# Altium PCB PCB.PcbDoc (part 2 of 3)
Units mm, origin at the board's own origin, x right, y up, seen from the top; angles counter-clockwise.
Board outline 43.18 x 22.86 mm, 6 copper layers (TOP, L2_GND, L3_SIG, L4_PWR, L5_GND, BOTTOM), stack 1.573 mm thick; 127 components, 116 nets, 532 pads, 386 vias.
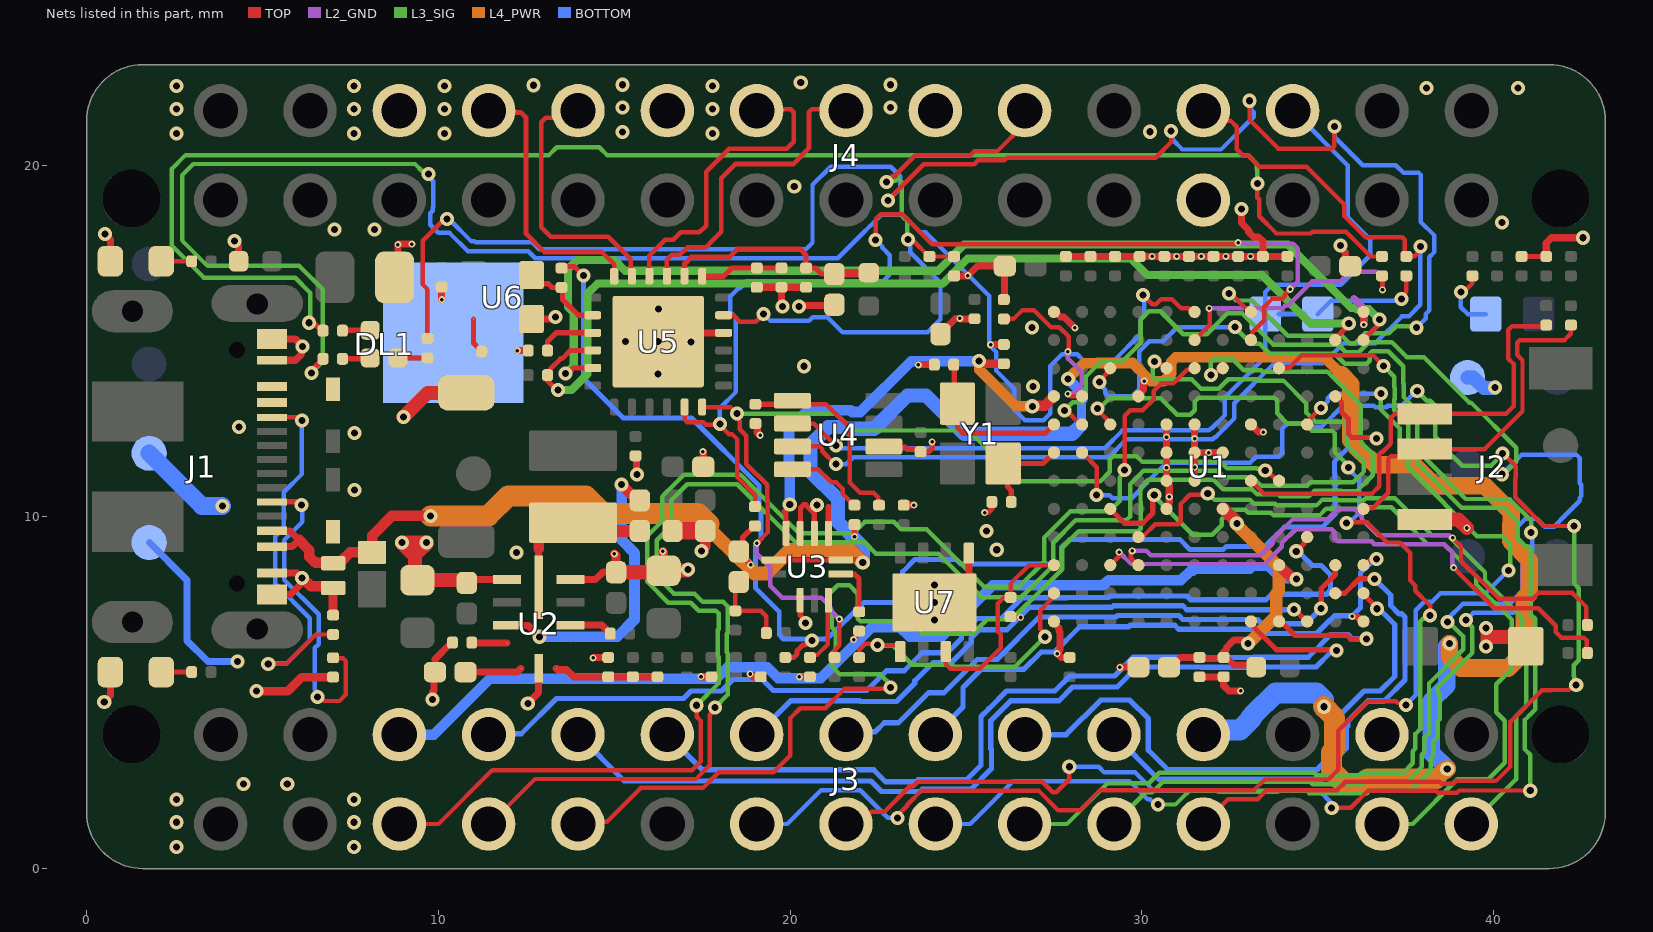
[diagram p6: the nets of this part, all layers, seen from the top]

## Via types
v1: diameter 0.4, hole 0.2, TOP to BOTTOM, tented both sides, 318 vias
v2: diameter 0.2, hole 0.1, TOP to L2_GND, tented both sides, 68 vias

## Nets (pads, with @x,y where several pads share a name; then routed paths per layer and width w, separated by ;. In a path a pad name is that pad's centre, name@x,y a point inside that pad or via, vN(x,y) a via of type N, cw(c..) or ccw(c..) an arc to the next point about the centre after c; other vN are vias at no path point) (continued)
+VBUS: D3.1 D8.A J1.A4 J1.A9 J1.B4 J1.B9 J3.23 TP_VUSB1.X U3.6 U3.11 | length 77.3
  TOP w0.15: U3.11@19.541,8.778 U3.6@21.436,8.778 ; U3.6@21.439,8.78 21.925,8.78 21.999,8.706 v1(22.066,8.706)
  TOP w0.2: J1.A9@5.276,9.155 5.844,9.155 6.039,9.35 5.784,9.605 J1.B4@5.276,9.605
  TOP w0.3: 6.039,9.35 6.333,9.056 6.333,8.87 6.508,8.695 6.966,8.695 7.005,8.733 7.233,8.733 7.494,8.994 D8.A@8.115,8.994 8.115,9.469 8.675,10.029 v1(9.772,10.029)
  L4_PWR w0.3: v1(27.902,13.927) 28.346,14.37 28.721,14.37 28.727,14.377 29.741,14.377 30.258,13.859 30.617,13.859 30.844,14.086 30.844,14.41 30.969,14.536 35.183,14.536 35.682,14.037
  L4_PWR w0.4: 17.7,9.8 17.7,9.677 18.649,8.728 18.657,8.728 18.994,8.391 19.325,8.391 19.99,9.055 21.718,9.055 v1(22.066,8.706)
  L4_PWR w0.5: 35.682,14.037 35.941,13.778 35.941,12.182 36.1,12.023 36.1,11.988 36.438,11.65 36.474,11.65 36.635,11.489 37.734,11.489 38.331,10.892 39.746,10.892 40.502,10.136 40.502,9.806 40.492,9.796 40.492,9.318 40.502,9.308 40.502,9.292 41.02,8.774 41.02,7.824 40.879,7.683 40.879,6.163 40.422,5.706 39.07,5.706 38.744,6.033 v1(38.744,6.396) ; 38.344,2.551 38.593,2.8 38.645,2.8 v1(38.684,2.84)
  L4_PWR w0.6: v1@9.773,10.029 11.417,10.029 11.987,10.599 14.201,10.599 14.7,10.1 17.4,10.1 17.7,9.8 ; v1(35.175,4.604) 35.477,4.302 35.477,3.395 35.39,3.308 35.39,2.789 35.757,2.422 36.3,2.422 36.429,2.551 38.344,2.551
  BOTTOM w0.25: 28.258,12.6 28.283,12.625 28.283,13.303 28.308,13.328
  BOTTOM w0.3: v1(27.902,13.927) 28.308,13.522 28.308,13.328
  BOTTOM w0.4: v1(22.066,8.706) 22.066,9.145 21.358,9.853 21.358,10.509 20.584,11.284 20.584,12.058 21.033,12.508 21.083,12.558 21.52,12.558 21.57,12.508 22.392,12.508 23.335,13.45 23.867,13.45 24.951,12.366 28.023,12.366 28.258,12.6
  BOTTOM w0.5: TP_VUSB1.X@1.778,11.811 3.276,10.313 v1(3.858,10.313) ; v1(38.684,2.84) 38.668,2.856 38.668,2.866 38.233,3.301 38.233,4.773 38.667,5.207 38.667,6.319 v1(38.744,6.396)
  BOTTOM w0.6: J3.23@31.75,3.81 31.88,3.94 32.792,3.94 33.103,4.251 33.103,4.302 33.179,4.377 33.179,4.38 33.798,5 34.963,5 35.168,4.795 35.168,4.613 35.176,4.605 v1(35.175,4.604)
A0_1: J3.7 U1.J10 | length 28.3
  TOP w0.15: v1(34.391,9.024) 34.398,9.024 34.611,9.237 34.611,9.285 34.702,9.376 U1.J10@34.702,9.43
  BOTTOM w0.15: J3.7@11.43,3.81 11.457,3.837 12.355,3.837 13.356,4.838 16.968,4.838 17.18,5.05 18.05,5.05 18.378,5.378 19.209,5.378 19.523,5.064 22.181,5.064 22.745,5.628 23.245,5.628 23.757,6.14 24.471,6.14 24.874,6.542 24.874,6.673 25.312,7.111 26.008,7.111 26.603,7.707 27.886,7.707 27.89,7.71 29.037,7.71 29.079,7.752 31.283,7.752 31.388,7.646 33.533,7.646 33.687,7.8 35.247,7.8 35.365,7.918 35.365,8.357 35.101,8.621 34.848,8.621 34.445,9.024 v1(34.391,9.024)
A1_1: J3.9 U1.M8 | length 27.6
  TOP w0.15: U1.M8@33.102,7.03 33.102,6.976 33.198,6.88 33.198,6.86 33.835,6.223 35.517,6.223 v1(35.54,6.199)
  BOTTOM w0.15: J3.9@13.97,3.81 15.285,2.495 22.303,2.495 22.602,2.195 23.695,2.195 23.758,2.258 25.139,2.258 25.726,2.844 25.726,3.394 25.708,3.412 25.708,4.208 25.925,4.426 25.925,4.429 26.269,4.772 27.639,4.772 28.035,5.168 29.301,5.168 29.869,5.736 31.687,5.736 31.699,5.724 33.298,5.724 33.309,5.736 34.957,5.736 35.373,6.151 35.492,6.151 v1(35.54,6.199)
A2_1: J3.11 U1.M9 | length 25.7
  TOP w0.15: U1.M9@33.902,7.03 33.957,7.03 34.356,6.63 35.313,6.63 35.318,6.635 35.833,6.635 35.943,6.525 36.382,6.525 v1(36.393,6.536)
  BOTTOM w0.15: J3.11@16.51,3.81 17.511,2.809 22.381,2.809 22.717,2.472 23.58,2.472 23.643,2.535 25.025,2.535 25.431,2.941 25.431,4.323 25.648,4.541 25.648,4.543 26.154,5.049 27.524,5.049 27.954,5.479 29.22,5.479 29.754,6.013 31.802,6.013 31.813,6.001 33.183,6.001 33.194,6.013 34.733,6.013 35.374,6.653 35.859,6.653 35.976,6.536 v1(36.393,6.536)
A3_1: J3.13 U1.M10 | length 17.5
  TOP w0.15: v1(34.333,7.363) 34.353,7.363 34.687,7.03 U1.M10@34.702,7.03
  BOTTOM w0.15: J3.13@19.05,3.81 20.012,4.772 21.988,4.772 22.008,4.753 23.027,4.753 23.548,5.274 23.548,5.342 24.069,5.863 24.586,5.863 25.151,6.427 25.151,6.558 25.386,6.793 26.164,6.793 26.8,7.43 28.001,7.43 28.005,7.433 29.152,7.433 29.193,7.475 31.168,7.475 31.279,7.363 v1(34.333,7.363)
A4_1: J3.15 U1.K11 | length 16.6
  TOP w0.15: v1(35.091,7.398) 35.103,7.41 35.103,7.964 35.502,8.363 U1.K11@35.502,8.63
  BOTTOM w0.15: J3.15@21.59,3.81 21.676,3.896 22.425,3.896 22.678,4.148 23.081,4.148 23.935,5.003 24.377,5.003 25.323,5.949 25.879,5.949 27.083,7.153 28.116,7.153 28.12,7.156 29.267,7.156 29.308,7.198 31.053,7.198 31.165,7.086 33.293,7.086 33.418,6.961 34.654,6.961 v1(35.091,7.398)
A5_1: J3.17 U1.K12 | length 16.2
  TOP w0.15: U1.K12@36.302,8.63 36.357,8.63 36.478,8.751 36.631,8.751 v1(36.679,8.799)
  BOTTOM w0.15: J3.17@24.13,3.81 24.915,4.595 24.915,5.149 25.437,5.672 26.65,5.672 27.142,6.163 27.518,6.163 28.234,6.879 29.629,6.879 29.67,6.921 30.938,6.921 31.054,6.805 33.183,6.805 33.304,6.684 34.97,6.684 35.268,6.983 ; 35.27,6.983 35.477,7.191 35.991,7.191 36.218,7.418 36.218,8.414 36.446,8.643 36.455,8.643 36.611,8.799 v1(36.679,8.799)
A6_1: J3.19 U1.L12 | length 16.7
  TOP w0.15: U1.L12@36.302,7.83 36.302,7.802 36.686,7.418 v1(36.686,7.39)
  BOTTOM w0.15: J3.19@26.67,3.81 27.85,3.81 28.835,4.796 29.656,4.796 30.186,4.265 30.186,3.368 30.738,2.816 34.987,2.816 35.338,3.167 35.338,3.337 35.496,3.495 35.496,4.072 35.589,4.165 35.589,4.308 35.678,4.397 35.678,4.413 35.878,4.613 36.316,5.051 36.778,5.051 37.193,5.466 37.193,6.939 36.743,7.39 v1(36.686,7.39)
A7_1: J3.21 U1.L11 | length 15.1
  TOP w0.15: U1.L11@35.502,7.83 35.769,7.83 36.18,8.241 v1(36.62,8.241)
  BOTTOM w0.15: J3.21@29.21,3.81 30.481,2.539 35.101,2.539 35.615,3.052 35.615,3.222 35.814,3.421 35.814,3.998 35.866,4.05 35.866,4.193 35.955,4.283 35.955,4.299 36.431,4.774 36.893,4.774 37.482,5.364 37.482,7.157 37.394,7.245 37.313,7.245 37.078,7.481 37.078,7.783 v1(36.62,8.241)
ANEN_SPEED: J4.19 R26.1 R30.1 U5.23 | length 18.2
  TOP w0.127: U5.23@18.11,15.735 18.393,15.735 18.574,15.554 19.025,15.554 v1(19.243,15.772) ; v1(22.747,19.526) 22.921,19.7 22.973,19.7 23.556,20.284 25.132,20.284 25.241,20.392 25.885,20.392 26.67,21.177 J4.19@26.67,21.59 ; v1(23.356,17.888) 23.408,17.835 23.52,17.835 23.95,17.406 R30.1@24.665,17.406
  L3_SIG w0.127: v1(22.747,19.526) 22.786,19.566 23.01,19.566 23.07,19.625 23.179,19.515 23.179,18.559 23.23,18.508 ; 23.23,18.508 23.336,18.402 23.336,17.907 v1(23.356,17.888)
  BOTTOM w0.127: v1(19.243,15.772) 19.443,15.572 20.533,15.572 20.641,15.68 21.062,15.68 21.492,15.25 23.907,15.25 24.277,15.62 24.277,16.668 23.419,17.526 23.419,17.751 23.356,17.814 v1(23.356,17.888)
AREF_1: J3.5 U1.K9 | length 28.8
  TOP w0.3: U1.K9@33.902,8.63 34.284,8.249 34.38,8.249 v1(34.399,8.23)
  BOTTOM w0.25: 31.446,8.475 31.471,8.5 33.076,8.5 33.162,8.586 33.591,8.586 33.947,8.23 v1(34.399,8.23)
  BOTTOM w0.3: J3.5@8.89,3.81 9.871,3.81 11.463,5.402 17.904,5.402 18.232,5.73 19.355,5.73 19.668,5.416 20.868,5.416 22.32,6.867 23.127,6.867 23.4,6.594 24.305,6.594 24.584,6.873 24.584,6.881 25.762,8.059 27.741,8.059 27.744,8.062 28.891,8.062 28.949,8.121 28.978,8.121 29.054,8.196 31.113,8.196 31.391,8.475 31.446,8.475
CANH_1: J4.23 R8.2 U4.7 | length 30.7
  TOP w0.127: U4.7@20.165,12.006 20.84,12.006 20.914,11.931 20.914,11.866 21.276,11.504 v1(21.305,11.504) ; J4.23@31.75,21.59 32.128,21.59 32.448,21.269 32.522,21.269 32.7,21.092 32.7,20.453 32.886,20.266 33.038,20.266 33.344,19.961 34.684,19.961 35.759,18.885 35.759,18.555 36,18.314 36.361,17.953 37.406,17.953 37.481,17.878 37.481,17.406 37.491,17.416 37.754,17.416 37.877,17.539 37.877,17.643 v1(37.929,17.695)
  BOTTOM w0.127: v1(21.305,11.504) 21.6,11.504 21.793,11.697 29.058,11.697 29.566,12.206 32.014,12.206 32.076,12.267 32.097,12.267 32.631,12.801 32.631,13.236 33.759,14.365 35.164,14.365 35.736,14.937 36.632,14.937 37.396,15.7 37.587,15.7 37.92,16.033 37.92,17.686 v1(37.929,17.695)
CANL_1: J4.25 SJ1.1 U4.6 | length 25.3
  TOP w0.127: U4.6@20.165,12.656 20.677,12.656 v1(21.302,12.031)
  BOTTOM w0.127: v1(21.302,12.031) 21.376,12.031 21.449,11.957 21.476,11.957 28.948,11.957 29.45,12.46 31.909,12.46 31.97,12.521 31.989,12.521 32.365,12.897 32.365,13.406 33.506,14.547 SJ1.1@33.506,15.769 33.506,16.396 33.707,16.596 35.653,16.596 36.5,17.443 36.5,17.879 35.859,18.52 35.859,19.994 J4.25@34.29,21.563
CC1_1: J1.A5 R10.2 | length 11.5
  TOP w0.127: v1(5.164,5.821) 5.674,5.821 6.511,6.658 R10.2@7.008,6.658 ; J1.A5@5.276,12.83 6.038,12.83 v1(6.121,12.747)
  BOTTOM w0.127: v1(5.164,5.821) 5.674,5.821 6.341,6.489 6.341,7.124 5.359,8.106 5.359,9.442 5.6,9.683 5.6,10.7 6.121,11.221 v1(6.121,12.747)
CC2_1: J1.B5 R9.2 | length 9.2
  TOP w0.127: v1(6.57,4.877) 6.644,4.877 6.753,4.767 7.186,4.767 7.37,4.95 7.37,5.902 7.295,5.976 7.113,5.976 R9.2@7.1,5.99
  TOP w0.15: J1.B5@5.276,10.43 5.951,10.43 6.043,10.338 v1(6.109,10.338)
  BOTTOM w0.127: v1(6.109,10.338) 6.133,10.314 6.133,9.857 5.613,9.337 5.613,8.212 6.595,7.229 6.595,6.383 6.489,6.277 6.489,5.088 6.517,5.059 6.517,4.929 v1(6.57,4.877)
ETH_RX_1_N: J4.15 U5.3 | length 8.8
  TOP w0.133: U5.3@16.495,16.851 16.495,17.313 16.519,17.338 16.632,17.451 16.864,17.451 17.072,17.659 17.6,17.659 17.793,17.852 18.047,18.106 18.047,19.636 18.444,20.034 20.086,20.034 20.537,20.484 20.537,21.512 20.615,21.59 J4.15@21.59,21.59
ETH_RX_1_P: J4.13 U5.4 | length 8.9
  TOP w0.133: U5.4@16,16.845 16,17.431 16.453,17.884 16.685,17.884 16.893,18.092 17.421,18.092 17.614,18.285 17.614,19.816 18.265,20.467 19.907,20.467 20.103,20.664 20.103,21.512 20.025,21.59 J4.13@19.05,21.59
ETH_TX_1_N: J4.9 U5.5 | length 7.6
  TOP w0.133: J4.9@13.97,21.59 13.726,21.346 13.053,21.346 12.926,21.219 12.926,18.234 13.194,17.966 14.83,17.966 15.105,17.692 15.231,17.565 15.467,17.329 15.467,16.879 U5.5@15.5,16.845
ETH_TX_1_P: J4.7 U5.6 | length 7.8
  TOP w0.133: J4.7@11.43,21.59 11.619,21.401 11.72,21.502 12.347,21.502 12.493,21.355 12.493,18.054 13.014,17.533 14.65,17.533 14.925,17.258 15.003,17.18 15.003,16.848 U5.6@15,16.845
GND: C1.1 C2.1 C3.1 C4.1 C5.1 C6.1 C7.1 C8.1 C9.2 C10.1 C11.1 C12.1 C13.1 C14.1 C17.1 C18.1 C20.2 C21.1 C23.1 C24.1 C25.2 C26.1 C27.1 C29.1 C30.1 C32.1 C33.1 C34.1 C35.1 C36.1 C37.1 C40.1 C42.1 C43.1 C44.1 C45.1 C46.1 C47.1 C48.1 C49.1 C51.1 D1.1 D2.1 D3.2 D6.1 DL2.C DL3.C GND1.X GND2.X J1.A1 J1.A12 J1.B1 J1.B12 J2.1 J3.27 J4.5 J4.11 J4.17 J4.24 PB1.1 QR1.PAD R4.1 R9.1 R10.1 R13.2 R15.2 R17.1 R21.2 R22.2 R29.1 R30.2 R31.2 R32.2 R33.1 R37.1 R42.2 R46.2 U1.A1 U1.A12 U1.D4 U1.E5 U1.E6 U1.E8 U1.F5 U1.F6 U1.F7 U1.G5 U1.G6 U1.H5 U1.M1 U1.M12 U2.1 U2.6 U2.11 U3.2 U4.2 U5.22 U5.25 U6.2 U7.5 U7.9 | length 80.6
  TOP w0.15: v2(18.879,8.638) 18.879,8.649 18.562,8.967 18.544,8.967 18.544,9.077 18.653,9.185 18.653,9.414 18.985,9.746 R29.1@19,9.746 ; v2(20.262,5.456) R42.2@20.565,5.456 ; U3.2@20.289,7.63 20.289,7.205 20.442,7.052 v1(20.442,6.986) ; v2(21.807,6.514) 21.807,6.527 21.873,6.594 21.873,6.676 21.953,6.756 C9.2@21.965,6.756 ; v2(21.832,9.439) R22.2@21.832,9.746 ; U4.2@22.665,12.006 22.69,11.98 23.274,11.98 23.327,11.926 23.644,11.926 C40.1@23.715,11.856 23.951,11.856 24.039,11.943 v2(24.039,12.133) ; v2(25.53,10.124) 25.54,10.134 25.636,10.134 25.738,10.235 C25.2@25.738,10.426 ; R37.1@26.269,7.165 26.292,7.141 v2(26.552,7.141) ; R46.2@40.8,17.406 C1.1@41.5,17.406
  TOP w0.2: v1@0.432,4.737 v1(0.5,4.737) 0.5,4.754 0.675,4.929 DL2.C@0.675,5.59 ; v1(0.52,18.051) 0.52,18.047 0.675,17.892 DL3.C@0.675,17.27 ; v1(4.202,17.841) 4.321,17.723 R4.1@4.321,17.27 ; J1.A12@5.276,7.795 5.801,7.795 6.083,8.078 6.083,8.168 6.122,8.206 v1(6.122,8.26) 6.122,8.267 6.001,8.388 5.995,8.388 5.979,8.405 J1.B1@5.276,8.405 ; J1.B12@5.276,14.455 5.933,14.455 6.105,14.627 6.105,14.814 v1(6.143,14.852) 5.93,15.065 J1.A1@5.276,15.065 ; C2.1@8.758,16.813 8.851,16.907 v2(8.851,17.741) 8.87,17.759 v2@9.198,17.759 ; v1(9.838,4.811) 9.838,5.024 9.87,5.056 9.87,5.557 C51.1@9.901,5.589 9.901,5.955 10.304,6.358 10.345,6.358 10.4,6.413 R15.2@10.4,6.428 ; C44.1@10.092,16.539 10.092,16.189 v2(10.099,16.182) ; C35.1@10.809,8.126 10.904,8.222 U2.1@11.952,8.222 ; v2(12.245,14.731) R33.1@12.554,14.731 ; v1(12.542,4.693) 12.852,5.003 U2.6@12.852,5.697 ; U6.2@12.647,15.625 13.273,15.625 v1(13.334,15.687) ; U2.11@13.752,8.222 14.472,8.222 14.678,8.428 C34.1@15.053,8.428 ; v2(14.398,5.996) 14.407,6.006 R17.1@14.829,6.006 ; C47.1@15.608,11.738 15.628,11.718 15.628,11.227 v1(15.648,11.207) ; v1(16.25,14.985) 16.5,15.235 U5.22@18.11,15.235 ; v2(17.468,5.463) 17.475,5.456 R31.2@17.764,5.456 ; v2(17.522,11.856) 17.531,11.847 C48.1@17.531,11.43 ; v2(18.861,5.535) 18.941,5.456 R32.2@19.164,5.456 ; R21.2@19.014,12.656 19.066,12.604 19.066,12.405 v2(19.149,12.323) ; C45.1@19.055,16.531 C46.1@19.755,16.531 ; v1(19.789,15.986) 19.755,16.02 C46.1@19.755,16.531 ; v1(20.258,15.983) 20.285,16.009 21.233,16.009 C43.1@21.259,16.035 ; C42.1@20.455,16.531 C46.1@19.755,16.531 ; C49.1@23.17,10.335 v2(23.52,10.335) ; v2(23.645,14.326) 23.649,14.33 C20.2@24.102,14.33 ; v1(24.107,7.571) 24.357,7.571 25.082,8.296 U7.5@25.082,8.971 ; C26.1@24.277,15.195 24.277,15.22 24.701,15.644 v2(24.826,15.644) 24.836,15.634 C27.1@25.245,15.634 ; R30.2@24.665,16.856 25.053,16.856 v2(25.058,16.861) 25.328,17.131 C6.1@26.106,17.131 26.091,17.116 26.091,16.194 R13.2@26.077,16.18 ; v2(25.704,14.896) 25.713,14.905 C30.1@26.077,14.905 ; U1.M1@27.502,7.03 27.502,6.989 27.646,6.845 27.646,6.758 27.68,6.725 27.68,6.204 v2(27.591,6.115) 27.701,6.006 C29.1@27.949,6.006 ; U1.A1@27.502,15.83 27.543,15.83 27.687,15.686 27.788,15.686 v2(28.098,15.376) ; C23.1@27.841,17.406 v2(30.291,17.406) C17.1@30.641,17.406 v2(30.991,17.406) v2(31.691,17.406) v2(32.391,17.406) v2(33.091,17.406) 33.724,17.406 ; v2(29.379,5.726) 29.384,5.731 C3.1@29.906,5.731 ; U1.D4@29.902,13.43 29.902,13.471 30.046,13.615 30.046,13.84 v2(30.07,13.864) ; U1.H5@30.702,10.23 30.702,10.271 30.777,10.346 30.777,10.411 30.781,10.415 v2(30.781,10.569) 30.781,10.911 30.702,10.989 U1.G5@30.702,11.03 v2(30.702,11.399) v2(30.702,12.273) U1.E5@30.702,12.63 ; U1.E6@31.488,12.63 U1.E6@31.502,12.63 v2(31.502,12.23) U1.F6@31.502,11.83 ; U1.G6@31.502,10.993 U1.G6@31.502,11.03 v2(31.502,11.415) U1.F6@31.502,11.83 ; C4.1@31.639,5.456 C5.1@32.329,5.456 32.329,5.201 32.476,5.054 v2(32.808,5.054) ; U1.F7@32.302,11.83 v2(31.902,11.83) U1.F6@31.502,11.83 ; v1(32.837,18.758) 32.837,18.352 33.032,18.158 33.032,18.109 33.177,17.963 33.324,17.963 33.441,17.846 C11.1@33.441,17.406 ; U1.E8@33.102,12.63 33.322,12.41 v2(33.458,12.41) ; 33.762,17.406 C7.1@34.141,17.406 ; v1(35.653,17.713) 35.653,17.659 35.791,17.521 35.791,17.215 C21.1@35.876,17.131 ; v2(35.978,7.174) 36.118,7.174 36.262,7.03 U1.M12@36.302,7.03 ; U1.A12@36.302,15.83 36.312,15.821 36.312,15.471 v2(36.31,15.471) ; C1.1@41.5,17.406 41.5,17.784 41.654,17.938 v1(42.546,17.938)
  TOP w0.25: v1(4.831,5.047) 5.718,5.047 6.117,5.445 R9.1@7.005,5.445 ; R10.1@7.008,7.208 D3.2@7.008,7.953 ; v2(15.003,8.951) 15.053,8.901 C34.1@15.053,8.428 ; v2(16.385,9.02) 16.407,8.997 C33.1@16.407,8.472
  TOP w0.3: v1(6.122,8.26) 6.149,8.26 6.378,8.031 6.931,8.031 D3.2@7.008,7.953 ; v1(17.477,9.026) 17.477,9.053 17.584,9.16 C36.1@17.584,9.602 ; v1(39.784,6.317) 39.775,6.325 39.775,6.517 ; v1(39.783,6.846) 39.775,6.838 39.775,6.517 ; 39.844,6.586 39.775,6.517 ; D6.1@40.656,6.586 D6.1@40.917,6.325
  TOP w0.4: v1(9.008,12.843) 9.695,13.53 PB1.1@10.794,13.53 ; 9.338,8.826 9.338,8.274 C32.1@9.408,8.203 10.731,8.203 C35.1@10.809,8.126 ; C34.1@15.053,8.428 16.363,8.428 C33.1@16.407,8.472 17.065,8.472 v1(17.095,8.502) ; J2.1@38.039,9.93 38.997,9.93 v2(39.241,9.686) ; 39.844,6.586 D6.1@40.656,6.586 ; v1(8.961,9.271) 8.977,9.254 8.977,9.237 9.212,9.003 9.421,9.003 9.655,9.237 9.655,9.263 v1(9.663,9.271) v1(8.961,9.271)
  TOP w0.5: C37.1@16.656,9.602 C36.1@17.584,9.602
  L2_GND w0.2: 36.038,16.205 36.312,15.931 36.312,15.471 v2(36.31,15.471)
  BOTTOM w0.2: GND1.X@1.783,9.271 2.848,8.206 2.848,6.492 3.453,5.887 v1(4.292,5.887)
  BOTTOM w0.4: GND2.X@39.263,13.961 39.425,13.961 39.725,13.661 40.028,13.661 v1(40.045,13.679)
  other v1: 2.56,0.62 7.6,0.62 2.56,1.32 7.6,1.32 2.56,1.969 7.6,1.969 4.456,2.405 5.703,2.405 24.107,7.071 24.107,8.071 12.225,8.987 25.876,9.068 25.579,9.6 7.616,10.771 7.616,12.384 4.337,12.564 26.902,13.71 16.243,14.058 20.397,14.285 17.178,14.978 15.323,14.993 26.874,15.389 16.258,15.913 7.05,18.178 8.19,18.178 40.246,18.366 20.119,19.401 2.56,20.9 7.6,20.9 10.18,20.9 17.79,20.9 15.23,20.94 30.232,20.952 2.56,21.6 7.6,21.6 10.17,21.6 17.79,21.6 15.23,21.64 22.85,21.64 38.1,22.2 40.7,22.2 2.56,22.249 7.6,22.249 10.18,22.249 17.79,22.249 12.711,22.274 15.23,22.289 22.85,22.289 20.303,22.349
  other v2: 9.248,17.759
INTRP: R24.2 U1.G9 U5.18 | length 27.2
  TOP w0.127: U5.18@17.5,13.125 18.306,13.125 18.545,12.886 18.545,12.753 18.57,12.728 18.57,12.496 18.758,12.308 18.758,11.501 19.347,10.912 19.347,10.496 19.36,10.483 19.36,9.559 v2(19.055,9.254) ; R24.2@21.264,6.006 21.269,6.01 21.269,6.217 21.4,6.349 v2(21.4,7.093) ; v1(33.51,11.323) 33.56,11.323 33.853,11.03 U1.G9@33.902,11.03
  L2_GND w0.127: v2(19.055,9.254) 19.055,8.954 19.436,8.573 19.436,8.044 19.78,7.7 20.892,7.7 21.139,7.453 21.139,7.354 v2(21.4,7.093)
  L3_SIG w0.127: v1(18.492,12.939) 21.288,12.939 21.354,12.873 21.371,12.873 21.786,12.458 25.072,12.458 26.516,11.014 28.825,11.014 29.093,11.281 29.093,11.643 29.173,11.724 29.859,11.724 30.019,11.564 32.247,11.564 32.432,11.379 33.261,11.379 33.265,11.375 33.458,11.375 v1(33.51,11.323)
MDC: U1.B12 U5.11 | length 29.2
  TOP w0.142: v1(13.62,14.082) 13.679,14.082 13.833,14.235 U5.11@14.39,14.235 ; U1.B12@36.302,15.03 36.302,15.041 36.706,15.444 36.706,15.564 v1(36.755,15.613)
  L3_SIG w0.231: v1(13.62,14.082) 13.628,14.082 13.848,14.302 13.848,15.799 13.684,15.963 13.684,17.049 13.944,17.308 15.005,17.308 15.312,17.001 24.201,17.001 24.943,17.743 34.156,17.743 34.347,17.551 34.347,17.546 35.946,15.947 36.068,15.947 36.11,15.904 36.464,15.904 v1(36.755,15.613)
MDIO: R25.2 U1.B11 U5.10 | length 29
  TOP w0.142: v1(13.397,13.604) 13.368,13.604 13.104,13.868 R25.2@13.104,14.031 13.182,14.109 13.182,14.207 13.477,14.502 13.52,14.502 13.754,14.735 U5.10@14.39,14.735 ; U1.B11@35.502,15.03 35.502,15.075 35.885,15.457 v1(35.885,15.504)
  L3_SIG w0.231: v1(13.397,13.604) 13.398,13.606 13.784,13.606 14.242,14.064 14.242,16.353 14.532,16.642 24.349,16.642 25.052,17.346 29.684,17.346 30.156,16.875 33.42,16.875 34.791,15.504 v1(35.885,15.504)
NetC3_2: C3.2 C4.2 C5.2 L1.2 U1.H7 | length 8.7
  TOP w0.2: C3.2@30.776,5.731 30.828,5.731 31.103,6.006 C4.2@31.639,6.006 31.669,5.976 32.3,5.976 C5.2@32.329,6.006 ; v1(33.016,6.403) 32.97,6.403 32.871,6.502 32.616,6.502 32.407,6.293 32.407,6.234 32.329,6.156 C5.2@32.329,6.006 ; L1.2@33.254,5.731 33.19,5.795 32.624,5.795 32.468,5.951 32.384,5.951 C5.2@32.329,6.006
  TOP w0.35: U1.H7@32.302,10.23 32.328,10.23 32.691,9.867 32.691,9.823 v1(32.7,9.813)
  L4_PWR w0.35: v1(32.7,9.813) 32.71,9.804 32.71,9.768 33.897,8.582 33.897,7.883 33.826,7.813 33.826,7.199 33.03,6.403 v1(33.016,6.403)
NetC9_1: C9.1 U3.5 | length 1.5
  TOP w0.15: U3.5@21.439,8.38 21.824,8.38 21.959,8.245 21.959,7.484 21.948,7.473 21.948,7.322 C9.1@21.965,7.306
NetC12_2: C12.2 R41.1 R45.2 | length 2.3
  TOP w0.127: R41.1@18.442,7.333 18.442,8.048 C12.2@18.544,8.151 ; R41.1@18.444,7.331 18.708,7.331 18.711,7.334 19.166,7.334 19.325,7.175 R45.2@19.325,6.7
NetC20_1: C20.1 U1.E1 Y1.3 | length 4.6
  TOP w0.15: C20.1@24.652,14.33 24.665,14.317 Y1.3@24.665,13.316 ; Y1.3@24.759,13.221 24.759,12.535 24.911,12.383 27.256,12.383 U1.E1@27.502,12.63
NetC25_1: C25.1 U1.F1 Y1.1 | length 2.8
  TOP w0.15: C25.1@26.288,10.426 26.289,10.427 26.289,10.751 26.188,10.852 26.188,11.392 Y1.1@26.059,11.521 27.194,11.521 U1.F1@27.502,11.83
NetC30_2: C30.2 U1.D1 U3.7 U3.8 U3.9 U3.10 | length 15.3
  TOP w0.15: 19.828,10.155 19.831,10.155 19.887,10.099 U3.10@19.887,9.531 ; U3.9@20.295,9.536 20.295,10.258 20.384,10.347 20.442,10.347 20.69,10.099 U3.8@20.689,9.53 ; U3.7@21.089,9.53 21.089,10.289 21.1,10.3
  TOP w0.25: v1(25.367,14.43) 25.407,14.43 25.483,14.355 C30.2@26.077,14.355
  TOP w0.3: v1(26.886,13.147) 26.904,13.164 27.236,13.164 U1.D1@27.502,13.43
  L4_PWR w0.3: v1(25.367,14.43) 25.386,14.411 25.386,14.183 26.422,13.147 v1(26.886,13.147)
  BOTTOM w0.3: v1@19.97,10.35 19.97,10.376 19.99,10.397 19.99,11.391 19.97,11.412 19.97,12.5 20.504,13.035 21.718,13.035 21.768,12.985 21.997,12.985 23.442,14.43 v1(25.367,14.43) ; v1@19.988,10.349 v1(19.99,10.35)
  other v1: 20.764,10.345
NetC31_1: C31.1 L5.1 U2.12 | length 4.2
  TOP w0.2: U2.12@12.852,7.997 12.852,9.092 12.858,9.098
  TOP w0.3: 12.858,9.098 12.858,9.411 13.283,9.836 L5.1@13.829,9.836
  TOP w0.35: L5.1@14.063,9.602 C31.1@15.698,9.602
NetC31_2: C31.2 U2.3 | length 8.5
  TOP w0.2: U2.3@12.018,6.918 12.556,6.918 v1(12.881,6.593)
  TOP w0.3: v1(15.206,10.92) 15.489,10.637 15.589,10.637 15.698,10.527 C31.2@15.698,10.522
  BOTTOM w0.3: v1(12.881,6.593) 15.087,6.593 15.577,7.083 15.577,8.976 15.22,9.332 15.22,10.906 v1(15.206,10.92)
NetC39_1: C39.1 R16.1 R17.2 U2.7 | length 3
  TOP w0.2: U2.7@13.352,5.697 13.393,5.656 13.648,5.656 13.848,5.456 R17.2@14.829,5.456 R16.1@15.529,5.456 C39.1@16.229,5.456
NetC42_2: C42.2 C43.2 L7.1 U5.2 | length 6.3
  TOP w0.15: U5.2@17,16.845 17,17.196 17.189,17.385 18.272,17.385 18.498,17.611 20.292,17.611 20.455,17.448 C42.2@20.455,17.081 20.718,17.081 20.894,16.905 C43.2@21.259,16.905
  TOP w0.25: C43.2@21.259,16.905 21.28,16.926 22.22,16.926 L7.1@22.241,16.948
NetC45_2: C45.2 C46.2 U5.1 | length 2.4
  TOP w0.15: U5.1@17.5,16.845 18.109,16.845 18.345,17.081 C45.2@19.055,17.081 C46.2@19.755,17.081
NetC51_2: C51.2 U2.5 | length 1.6
  TOP w0.2: C51.2@10.771,5.589 12.244,5.589 U2.5@12.352,5.697
NetDL1_2: DL1.2 R5.2 | length 0.8
  TOP w0.15: DL1.2@8.853,14.518 9.686,14.518 R5.2@9.689,14.521
NetDL1_3: DL1.3 R7.2 | length 0.8
  TOP w0.15: R7.2@7.274,14.496 8.041,14.496 DL1.3@8.063,14.518
NetDL1_4: DL1.4 R6.2 | length 0.8
  TOP w0.15: R6.2@7.274,15.296 7.286,15.308 DL1.4@8.063,15.308
NetDL2_A: DL2.A R3.1 | length 0.9
  TOP w0.15: DL2.A@2.125,5.59 R3.1@2.986,5.59
NetDL3_A: DL3.A R2.1 | length 0.9
  TOP w0.127: DL3.A@2.125,17.27 R2.1@2.986,17.27
NetJ2_3: J2.3 R40.1 U1.H12 | length 10.1
  TOP w0.127: U1.H12@36.302,10.23 36.321,10.249 36.566,10.249 37.008,10.691 37.008,11.646 37.082,11.72 37.83,11.72 J2.3@38.039,11.93 39.749,11.93 40.824,13.005 40.824,14.455 40.675,14.604 40.675,14.956 40.749,15.03 42.02,15.03 42.2,15.21 R40.1@42.2,15.456
NetJ2_4: J2.4 R20.1 U1.G8 | length 13
  TOP w0.127: U1.G8@33.102,11.03 33.468,10.664 36.548,10.664 36.754,10.871 36.754,11.786 36.804,11.836 36.839,11.836 37.068,12.065 37.068,12.083 37.074,12.09 37.074,12.309 37.078,12.313 37.078,12.655 37.074,12.659 37.074,12.803 37.201,12.93 J2.4@38.039,12.93 40.355,12.93 40.57,13.145 40.57,14.35 40.421,14.499 40.421,15.319 40.53,15.428 41.474,15.428 R20.1@41.5,15.454
NetJ3_6: J3.6 U1.C6 | length 40.3
  TOP w0.127: J3.6@8.89,1.27 10.002,1.27 11.535,2.803 17.217,2.803 17.464,3.05 17.464,4.2 17.345,4.318 v1(17.345,4.647) ; v1(29.502,11.333) 29.513,11.344 29.513,12.876 29.67,13.033 30.022,13.033 30.337,13.348 30.337,13.581 30.551,13.796 30.894,13.796 31.286,14.187 31.46,14.187 U1.C6@31.502,14.23
  L3_SIG w0.127: v1(17.345,4.647) 17.966,5.267 17.966,6.026 17.947,6.045 17.947,6.789 17.966,6.808 17.966,7.257 17.892,7.331 17.407,7.331 17.177,7.561 16.537,7.561 15.943,8.154 15.943,9.462 16.367,9.886 16.367,10.58 16.992,11.205 18.584,11.205 20.257,9.531 21.799,9.531 22.128,9.86 22.947,9.86 23.163,9.644 23.887,9.644 25.51,8.021 26.52,8.021 27.224,8.725 27.224,9.414 27.972,10.162 29.085,10.162 29.367,10.444 29.367,11.124 29.502,11.259 v1(29.502,11.333)
NetJ3_8: J3.8 U1.C5 | length 49.2
  TOP w0.127: J3.8@11.43,1.27 11.47,1.27 12.749,2.549 17.323,2.549 17.718,2.945 17.718,4.376 17.869,4.527 v1(17.869,4.587) ; v1(30.367,14.425) 30.419,14.373 30.508,14.373 30.651,14.23 U1.C5@30.702,14.23
  L3_SIG w0.127: v1(17.869,4.587) 18.222,4.941 18.222,6.129 18.201,6.15 18.201,6.684 18.222,6.705 18.222,7.457 18.095,7.585 17.512,7.585 17.282,7.815 16.698,7.815 16.205,8.307 16.205,9.337 16.621,9.753 16.621,10.475 17.074,10.928 18.501,10.928 20.152,9.277 22.119,9.277 22.442,8.954 24.218,8.954 25.451,7.721 26.569,7.721 26.633,7.785 26.643,7.785 27.481,8.622 27.481,9.271 28.118,9.908 29.562,9.908 29.666,10.012 29.666,10.93 30.046,11.31 32.142,11.31 32.327,11.125 33.156,11.125 33.387,10.893 34.7,10.893 34.799,10.993 35.777,10.993 35.781,10.989 36.011,10.989 36.316,11.295 36.316,11.558 35.825,12.049 35.825,12.635 35.751,12.709 34.938,12.709 34.68,12.968 34.68,13.226 34.026,13.879 33.323,13.879 33.286,13.916 32.46,13.916 32.192,13.648 31.684,13.648 31.416,13.916 30.392,13.916 30.317,13.991 30.317,14.376 v1(30.367,14.425)
NetJ3_10: J3.10 U1.C7 | length 42.8
  TOP w0.127: J3.10@13.97,1.27 14.038,1.338 14.794,1.338 15.751,2.295 17.522,2.295 17.969,2.742 19.53,2.742 20.001,3.212 20.001,4.272 20.288,4.56 20.996,4.56 21.546,5.11 22.815,5.11 v1(22.86,5.155) ; v1(31.967,14.039) 32.019,14.091 32.104,14.091 32.243,14.23 U1.C7@32.302,14.23
  L3_SIG w0.127: v1(22.86,5.155) 22.86,5.226 22.564,5.523 21.422,5.523 21.184,5.76 21.184,6.113 21.292,6.221 21.292,6.755 21.184,6.862 21.184,7.352 21.125,7.41 21.125,7.823 21.357,8.055 21.689,8.055 21.928,7.816 21.928,7.109 22.002,7.035 23.418,7.035 23.773,6.68 25.189,6.68 25.602,7.093 26.3,7.093 26.738,7.531 26.748,7.531 27.735,8.517 27.735,9.122 28.203,9.591 29.89,9.591 29.964,9.665 29.964,10.43 ; 29.964,10.43 29.964,10.754 29.964,10.839 30.181,11.056 32.037,11.056 32.31,10.783 33.139,10.783 33.282,10.639 33.887,10.639 33.939,10.588 34.753,10.588 34.904,10.739 35.672,10.739 35.675,10.735 36.116,10.735 36.57,11.189 36.57,11.785 36.519,11.836 36.516,11.836 36.287,12.065 36.287,12.068 36.222,12.134 36.222,13.183 35.271,14.133 33.428,14.133 33.391,14.17 32.903,14.17 32.572,14.501 32.073,14.501 31.967,14.395 v1(31.967,14.039)
NetJ3_14: J3.14 U1.E10 | length 37.2
  TOP w0.127: v1(23.057,1.444) 23.057,1.517 23.329,1.79 23.329,1.813 23.736,2.221 27.064,2.221 27.62,1.665 28.244,1.665 28.813,2.234 33.192,2.234 33.493,2.535 35.305,2.535 35.591,2.821 35.591,3.918 36.435,4.763 37.222,4.763 37.274,4.711 37.457,4.711 v1(37.51,4.658) ; U1.E10@34.702,12.63 34.702,12.69 34.819,12.807 34.819,12.826 35.093,13.1 v1(35.1,13.1)
  L3_SIG w0.127: v1(36.797,13.516) 36.79,13.508 36.79,13.064 37.328,12.525 37.328,11.857 37.577,11.608 37.577,11.416 38.617,10.375 38.617,10.361 39.53,9.448 40.253,9.448 40.455,9.246 40.455,9.172 40.48,9.147 40.48,8.727 40.478,8.725 40.478,8.535 v1(40.426,8.483)
  BOTTOM w0.127: J3.14@19.05,1.27 19.922,1.27 20.881,2.23 21.995,2.23 22.781,1.444 v1(23.057,1.444) ; v1(35.1,13.1) 35.288,13.288 35.288,13.375 35.416,13.503 36.784,13.503 v1(36.797,13.516) ; v1(37.51,4.658) 37.79,4.938 37.79,7.346 38.033,7.59 38.252,7.59 38.486,7.824 39.768,7.824 v1(40.426,8.483)
NetJ3_16: J3.16 U1.C9 | length 39.5
  TOP w0.127: J3.16@21.59,1.27 21.967,1.27 22.309,1.612 22.674,1.612 23.404,2.343 23.499,2.343 23.631,2.475 27.169,2.475 27.467,2.177 27.572,2.177 27.938,2.543 v1(27.938,2.898) ; U1.C9@33.902,14.23 34.186,14.23 34.551,14.596 36.574,14.596 v1(36.873,14.297) ; v1(35.4,1.731) 35.943,1.731 36.433,2.221 38.356,2.221 38.419,2.157 38.953,2.157 39.019,2.223 41.038,2.223 v1(41.044,2.216)
  L3_SIG w0.127: v1(36.873,14.297) 37.18,13.989 37.18,13.685 37.188,13.677 37.188,13.354 37.18,13.346 37.18,13.033 37.582,12.631 37.582,11.962 37.831,11.713 37.831,11.521 39.095,10.256 40.31,10.256 40.679,9.887 40.679,9.395 40.908,9.167 40.978,9.167 41.065,9.079 41.065,7.228 41.19,7.104 41.19,4.526 41.054,4.391 41.054,4.39 40.894,4.229 40.894,3.389 41.044,3.239 v1(41.044,2.216)
  BOTTOM w0.127: v1(27.938,2.898) 27.941,2.901 28.772,2.901 28.928,2.745 29.808,2.745 30.331,2.222 32.142,2.222 32.18,2.184 33.86,2.184 33.896,2.221 35.036,2.221 35.4,1.857 v1(35.4,1.731)
NetJ3_18: J3.18 U1.C3 | length 42.9
  TOP w0.127: v1(28.804,13.833) 28.804,13.882 29.102,14.181 U1.C3@29.102,14.23
  L3_SIG w0.127: v1(30.465,1.819) 30.471,1.824 30.957,1.824 31.283,2.15 31.286,2.15 31.356,2.221 34.684,2.221 34.754,2.15 36.406,2.15 36.478,2.223 37.65,2.223 38.214,2.786 38.214,3.131 38.289,3.206 38.289,3.619 38.419,3.75 38.419,4.204 38.469,4.254 38.469,4.969 38.419,5.019 38.419,5.16 39.393,6.134 39.393,6.707 ; v1(32.644,15.397) 32.644,15.391 33.108,14.928 33.352,14.928 33.638,14.642 33.717,14.642 33.717,14.641 35.482,14.641 35.77,14.352 36.394,14.352 36.482,14.44 36.482,14.64 36.556,14.715 37.007,14.715 37.434,14.287 37.434,13.79 37.442,13.783 37.442,13.409 37.836,13.015 37.836,12.067 38.085,11.818 38.085,11.638 39.213,10.51 40.456,10.51 41.069,9.897 v1(41.069,9.557) ; v1(39.223,7.071) 39.223,7.037 39.393,6.867 39.393,6.708
  BOTTOM w0.127: J3.18@24.13,1.27 25.125,1.27 26.346,2.491 29.648,2.491 30.171,1.968 30.242,1.968 30.392,1.819 v1(30.465,1.819) ; v1(28.804,13.833) 28.804,13.77 28.958,13.615 28.958,13.519 29.048,13.43 29.72,13.43 29.934,13.644 29.934,14.715 30.211,14.992 30.603,14.992 31.008,15.397 v1(32.644,15.397) ; v1(39.223,7.071) 39.431,7.278 40.566,7.278 41.105,7.818 41.105,9.521 v1(41.069,9.557)
NetJ3_20: J3.20 U1.E3 | length 32.2
  TOP w0.127: v1(28.738,13.084) 28.738,13.039 29.102,12.675 U1.E3@29.102,12.63 ; v1(35.816,9.823) 35.837,9.843 36.406,9.843 36.976,9.273 37.335,9.273 37.635,8.974 37.635,8.196 37.779,8.051 37.779,7.898 38.195,7.482 v1(38.195,7.199)
  L3_SIG w0.127: J3.20@26.67,1.27 27.872,1.27 28.257,1.655 28.257,1.665 29.016,2.424 30.004,2.424 30.008,2.427 30.196,2.427 30.498,2.729 34.894,2.729 34.965,2.658 36.179,2.658 36.251,2.731 37.44,2.731 37.706,2.997 37.706,3.342 37.781,3.416 37.781,3.829 37.911,3.96 37.911,5.371 37.92,5.379 37.92,7.028 37.994,7.102 38.024,7.102 38.121,7.199 v1(38.195,7.199) ; v1(28.738,13.084) 28.789,13.084 29.086,13.381 30.529,13.381 30.604,13.306 31.004,12.906 31.381,12.906 31.507,13.033 31.507,13.28 31.621,13.394 33.637,13.394 33.641,13.39 33.773,13.39 33.848,13.316 33.848,12.947 34.142,12.653 34.635,12.653 34.832,12.455 35.407,12.455 35.481,12.381 35.481,11.85 35.871,11.46 v1(35.871,11.401)
  BOTTOM w0.127: v1(35.816,9.823) 35.888,9.823 36.177,10.112 36.177,11.066 35.871,11.373 v1(35.871,11.401)
NetJ3_22: J3.22 U1.E2 | length 43.4
  TOP w0.127: v1(27.806,13.03) 27.854,13.03 28.254,12.63 U1.E2@28.302,12.63
  L3_SIG w0.127: v1(27.806,13.03) 28.038,13.262 28.29,13.262 28.413,13.385 28.413,13.995 28.826,14.408 29.434,14.408 29.971,14.945 29.971,15.623 30.2,15.852 30.523,15.852 31.177,15.198 31.849,15.198 32.439,15.788 32.851,15.788 33.738,14.901 33.816,14.901 33.823,14.895 35.587,14.895 35.795,14.687 36.169,14.687 36.451,14.969 37.112,14.969 37.538,14.543 38.024,14.543 39.313,13.253 39.358,13.253 40.648,11.964 40.648,11.564 40.298,11.214 v1(40.24,11.214) ; J3.22@29.21,1.27 30.113,2.173 30.302,2.173 30.603,2.475 34.789,2.475 34.859,2.404 36.284,2.404 36.356,2.477 37.545,2.477 37.96,2.891 37.96,3.237 38.035,3.311 38.035,3.724 38.165,3.855 38.165,5.265 39.139,6.239 39.139,6.602 38.727,7.014 v1(38.688,7.014)
  BOTTOM w0.127: v1(38.688,7.014) 38.688,7.088 39.132,7.532 40.461,7.532 40.817,7.888 40.817,8.781 40.751,8.847 40.751,9.323 40.679,9.395 40.679,9.719 40.908,9.948 41.231,9.948 41.453,9.726 41.725,9.726 41.899,9.9 41.899,9.905 42.455,10.461 42.455,10.539 42.466,10.549 42.466,10.566 42.495,10.596 42.495,10.919 42.455,10.959 42.455,11.676 42.358,11.774 40.8,11.774 v1(40.24,11.214)
NetJ3_24: J3.24 U1.F2 | length 37.4
  TOP w0.127: U1.F2@28.302,11.83 28.722,11.411 28.722,10.627 v1(28.718,10.623) ; J3.24@31.75,1.27 32.46,1.98 33.297,1.98 33.548,2.231 35.551,2.231 35.795,2.475 38.46,2.475 38.525,2.411 38.848,2.411 38.93,2.493 40.069,2.493 40.481,2.905 40.481,4.178 41.376,5.074 41.662,5.074 41.668,5.08 42.14,5.08 42.278,5.218 v1(42.352,5.218) ; v1(40.257,11.802) 40.276,11.802 40.631,11.447 40.631,11.113 40.616,11.098 40.616,10.563 41.435,9.743 v1(42.29,9.743)
  L3_SIG w0.127: v1(37.832,13.579) 38.105,13.306 38.201,13.306 38.344,13.163 38.344,12.277 38.593,12.029 38.593,11.976 39.112,11.457 39.931,11.457 40.257,11.783 v1(40.257,11.802) ; v1(42.29,9.743) 42.29,8.111 42.426,7.974 42.426,5.93 42.281,5.785 42.281,5.478 42.3,5.459 42.3,5.271 v1(42.352,5.218)
  BOTTOM w0.127: v1(28.718,10.623) 29.084,10.623 29.172,10.536 29.714,10.536 30.15,10.971 30.15,10.987 30.7,11.537 33.079,11.537 33.255,11.713 33.888,11.713 33.989,11.814 33.989,12.5 34.142,12.653 34.57,12.653 34.653,12.57 35.122,12.57 35.713,13.161 36.6,13.161 36.635,13.125 36.959,13.125 36.994,13.161 37.383,13.161 37.801,13.579 v1(37.832,13.579)
NetJ3_28: J3.28 U1.H3 | length 23.3
  TOP w0.15: U1.H3@29.102,10.23 29.511,9.822 30.027,9.822 30.315,10.109 30.315,10.584 v1(30.354,10.623)
  L3_SIG w0.127: v1(30.354,10.623) 30.354,10.592 31.452,9.494 32,9.494 32.269,9.763 32.269,9.935 32.539,10.204 32.942,10.204 33.022,10.124 33.664,10.124 33.745,10.043 35.052,10.043 35.24,10.231 35.462,10.231 35.465,10.227 36.42,10.227 36.471,10.278 37.093,10.278 37.322,10.05 37.322,10.032 38.123,9.231 38.592,9.231 39.504,8.318 39.504,8.094 40.516,7.083 40.516,5.676 40.31,5.47 40.309,5.47 40.08,5.241 40.08,4.917 ; J3.28@36.83,1.27 37.7,1.27 38.97,2.54 39.85,2.54 40.321,3.01 40.321,4.204 40.081,4.444 40.081,4.917
NetJ3_30: J3.30 U1.J4 | length 20.1
  TOP w0.127: U1.J4@29.902,9.43 29.945,9.473 30.061,9.473 30.384,9.796 31.029,9.796 31.104,9.87 31.104,10.37 31.364,10.631 31.84,10.631 v1(31.875,10.665)
  L3_SIG w0.127: v1(31.875,10.665) 31.89,10.665 32.069,10.486 33.076,10.486 33.184,10.378 33.79,10.378 33.841,10.326 34.967,10.326 35.125,10.485 35.567,10.485 35.57,10.481 36.314,10.481 36.366,10.532 37.198,10.532 38.246,9.485 38.702,9.485 39.758,8.429 39.758,8.199 40.815,7.143 40.815,6.532 40.936,6.411 40.936,4.632 40.8,4.496 40.8,4.495 40.64,4.335 40.64,2.54 J3.30@39.37,1.27
NetR5_1: R5.1 U1.A8 | length 51.3
  TOP w0.127: R5.1@9.69,15.072 9.69,16.476 9.556,16.61 9.556,17.852 10.171,18.467 v1(10.241,18.467) ; v1(22.789,19.001) 22.789,19.016 23.803,20.03 25.237,20.03 25.346,20.138 26.095,20.138 26.171,20.215 30.393,20.215 30.831,20.652 v1(30.831,20.969) ; v1(32.475,16.356) 32.526,16.356 33.052,15.83 U1.A8@33.102,15.83 ; v1(33.068,21.833) 33.068,21.285 33.885,20.469 34.894,20.469 34.9,20.463 35.4,20.463 35.474,20.538 v1(35.474,21.101)
  L3_SIG w0.127: v1(32.475,16.356) 32.677,16.154 33.141,16.154 34.146,15.149 35.692,15.149 35.9,14.941 36.064,14.941 36.346,15.223 37.028,15.223 37.231,15.426 37.766,15.426 v1(37.811,15.38)
  BOTTOM w0.127: v1(10.241,18.467) 10.307,18.467 10.93,17.843 11.023,17.843 11.059,17.808 12.66,17.808 12.862,17.606 20.445,17.606 20.638,17.798 20.638,19.445 21.153,19.961 22.865,19.961 23.137,19.688 23.137,19.349 v1(22.789,19.001) ; v1(30.831,20.969) 30.882,20.918 30.882,20.721 31.156,20.447 32.249,20.447 33.181,21.379 33.181,21.506 33.118,21.57 33.118,21.784 v1(33.068,21.833) ; v1(35.474,21.101) 35.474,20.812 36.284,20.002 37.225,20.002 37.446,19.781 37.879,19.781 37.925,19.735 37.925,18.397 38.32,18.002 38.32,17.533 38.174,17.388 38.174,15.872 38.068,15.766 38.068,15.637 v1(37.811,15.38)
NetR6_1: R6.1 R38.1 | length 44.9
  TOP w0.127: v1(33.289,19.479) 33.289,19.078 33.338,19.029 33.338,18.549 33.827,18.06 34.799,18.06 34.843,18.104 35.814,18.104 36.512,17.406 R38.1@36.829,17.406
  TOP w0.15: v1(6.322,15.522) 6.37,15.474 6.502,15.474 6.589,15.387 6.644,15.387 6.724,15.308 R6.1@6.724,15.296
  L3_SIG w0.127: v1(6.322,15.522) 6.353,15.553 6.353,16.376 5.927,16.802 3.334,16.802 2.417,17.719 2.417,19.895 2.811,20.289 13.144,20.289 13.365,20.51 14.575,20.51 14.796,20.289 32.863,20.289 32.886,20.266 33.038,20.266 33.267,20.038 33.267,19.885 33.289,19.863 v1(33.289,19.479)
NetR7_1: R7.1 U1.A6 | length 48.2
  TOP w0.127: v1@30.032,16.313 30.298,16.047 30.403,16.047 30.551,16.196 30.854,16.196 31.122,15.927 31.345,15.927 31.442,15.83 U1.A6@31.502,15.83
  TOP w0.15: v1(6.391,14.096) 6.391,14.163 6.632,14.404 6.644,14.404 6.724,14.484 R7.1@6.724,14.496
  L3_SIG w0.127: v1(6.391,14.096) 6.712,14.417 6.712,16.472 6.049,17.136 3.439,17.136 2.713,17.862 2.713,19.713 3.035,20.035 9.336,20.035 9.525,19.847 9.554,19.847 9.651,19.749 v1(9.725,19.749)
  BOTTOM w0.127: v1(9.725,19.749) 9.725,19.675 9.854,19.546 9.854,18.815 9.842,18.803 9.842,18.706 9.771,18.635 9.771,18.309 10,18.081 10.075,18.081 10.08,18.076 10.319,18.076 10.841,17.554 12.555,17.554 12.757,17.352 21.356,17.352 22.041,18.037 22.041,18.041 22.27,18.27 22.271,18.271 22.273,18.273 22.277,18.273 22.614,18.61 23.186,18.61 23.707,18.088 23.86,18.088 25.658,16.291 25.658,14.894 25.866,14.686 25.866,14.151 26.378,13.64 26.378,13.054 26.675,12.756 27.215,12.756 27.391,12.932 27.391,14.281 27.733,14.623 28.165,14.623 28.326,14.462 29.227,14.462 29.971,15.206 29.971,15.623 30.068,15.72 30.068,16.277 v1(30.029,16.316)
NetR8_1: R8.1 SJ1.2 | length 3.3
  TOP w0.127: v1(37.388,16.195) 37.388,16.269 37.525,16.406 37.525,16.818 R8.1@37.488,16.856
  BOTTOM w0.127: SJ1.2@35.006,15.769 35.381,16.144 37.337,16.144 v1(37.388,16.195)
NetR11_2: R11.2 U1.K3 | length 16.5
  TOP w0.127: U1.K3@29.102,8.63 29.343,8.87 29.343,8.986 v2(29.357,9) ; v2(38.863,8.556) 40.013,7.407 41.271,7.407 41.774,6.905 41.774,6.727 41.932,6.568 42.571,6.568 42.645,6.494 42.645,6.153 R11.2@42.669,6.128
  L2_GND w0.127: v2(29.357,9) 29.694,8.662 33.489,8.662 33.979,9.151 33.979,9.258 34.374,9.653 35.394,9.653 35.468,9.579 35.468,9.411 35.576,9.303 36.535,9.303 36.613,9.224 38.591,9.224 38.702,9.113 38.715,9.113 38.832,8.996 38.832,8.64 38.849,8.622 38.849,8.57 v2(38.863,8.556)
NetR12_2: R12.2 U1.K4 | length 16.2
  TOP w0.127: v2(29.729,9.038) 29.729,9.019 29.69,8.979 29.69,8.842 U1.K4@29.902,8.63 ; v2(38.835,9.404) 39.075,9.164 39.075,9.144 ; 39.076,9.143 39.076,8.754 40.154,7.676 41.116,7.676 41.279,7.839 42.24,7.839 42.642,7.438 42.642,6.956 R12.2@42.669,6.928
  L2_GND w0.127: v2(29.729,9.038) 30.132,9.038 30.254,8.916 33.384,8.916 33.725,9.257 33.725,9.363 34.302,9.94 35.291,9.94 35.564,10.213 36.061,10.213 36.249,10.024 36.249,9.947 36.718,9.478 38.741,9.478 38.815,9.404 v2(38.835,9.404)
NetR13_1: R13.1 U1.D2 | length 4.7
  TOP w0.127: R13.1@26.077,15.63 26.352,15.63 26.606,15.883 26.932,15.883 27.42,15.396 27.654,15.396 27.929,15.12 v2@27.929,14.7 ; v2(27.898,13.5) 27.91,13.5 27.98,13.43 U1.D2@28.302,13.43
  L2_GND w0.127: v2(27.898,13.5) 27.911,13.512 28.043,13.512 28.298,13.767 28.298,14.105 27.9,14.504 v2(27.9,14.7)
NetR14_2: R14.2 U2.9 | length 1.2
  TOP w0.2: U2.9@13.752,6.922 14.648,6.922 14.818,6.752 14.833,6.752 14.888,6.697 R14.2@14.888,6.682
NetR15_1: R15.1 U2.4 | length 1
  TOP w0.2: R15.1@10.95,6.428 10.956,6.422 U2.4@11.952,6.422
NetR18_1: R18.1 U5.8 U6.3 | length 2.4
  TOP w0.15: U6.3@12.647,16.875 12.893,16.629 13.131,16.629 13.235,16.525 R18.1@13.503,16.525 13.529,16.499 13.529,16.186 13.98,15.735 U5.8@14.39,15.735
NetR18_2: R18.2 R19.2 U1.D11 | length 39
  TOP w0.14: R18.2@13.503,17.075 13.547,17.119 13.865,17.119 14.119,16.866 v1(14.127,16.866) ; R19.2@19.865,6.006 20.105,6.006 20.198,6.099 20.198,6.195 20.33,6.328 20.337,6.328 20.366,6.358 20.428,6.358 20.558,6.488 v1(20.628,6.488) ; U1.D11@35.502,13.43 35.676,13.256 35.676,12.982 35.874,12.784 35.874,12.364 35.981,12.258 36.646,12.258 v1(36.677,12.227)
  BOTTOM w0.14: v1(14.127,16.866) 14.127,13.941 15.253,12.814 17.196,12.814 19.111,10.898 19.111,10.237 19.17,10.178 19.17,9.369 19.013,9.212 19.013,7.989 19.693,7.308 19.693,6.646 19.814,6.526 20.59,6.526 20.618,6.498 v1(20.628,6.488) ; v1@20.653,6.533 21.06,6.533 22.094,7.567 23.12,7.567 23.202,7.649 23.202,8.446 23.552,8.795 24.718,8.795 24.851,8.663 27.633,8.663 27.715,8.745 27.715,9.13 27.947,9.363 31.08,9.363 31.367,9.076 32.317,9.076 32.403,9.162 33.498,9.162 34.048,9.712 35.131,9.712 35.492,10.073 35.492,11.219 35.474,11.237 35.474,11.566 36.17,12.262 36.642,12.262 v1(36.677,12.227)
NetR21_1: R21.1 R43.2 U4.5 | length 5.7
  TOP w0.127: U4.5@20.065,13.206 21.021,13.206 21.354,12.873 21.371,12.873 21.695,12.548 21.695,10.979 21.988,10.686 22.374,10.686 22.507,10.553 22.507,10.359 R43.2@22.532,10.335
  TOP w0.15: R21.1@19.014,13.206 U4.5@20.065,13.206
NetR22_1: R22.1 U4.8 | length 2.3
  TOP w0.127: U4.8@20.065,11.356 20.796,11.356 21.168,10.983 21.308,10.983 21.492,10.799 21.492,10.659 21.817,10.335 R22.1@21.832,10.335
NetR29_2: R29.2 U1.B8 U5.17 | length 30.5
  TOP w0.127: U5.17@17,13.125 17,12.775 17.081,12.695 17.537,12.695 17.606,12.626 v1@17.991,12.626 ; v1(18.004,12.639) v1@17.991,12.626 ; R29.2@19,10.296 19.01,10.306 19.01,10.616 18.504,11.122 18.504,12.202 18.349,12.357 18.26,12.357 v1@17.991,12.626 ; v1(22.431,17.88) 22.431,18.468 22.574,18.61 23.186,18.61 24.045,17.751 30.838,17.751 32.67,17.751 32.719,17.8 v2(32.738,17.8) ; U1.B8@33.102,15.03 33.143,15.071 33.143,15.252 33.482,15.592 33.482,15.977 33.704,16.199 33.991,16.199 34.066,16.273 34.066,16.322 v2(34.217,16.474)
  L2_GND w0.127: v2(32.738,17.8) 32.904,17.8 32.936,17.767 34.298,17.767 34.434,17.631 34.434,16.691 v2(34.217,16.474)
  BOTTOM w0.127: v1(18.004,12.639) 18,12.643 18,13.093 18.46,13.553 18.46,15.668 18.304,15.824 18.304,16.279 18.532,16.506 18.567,16.506 18.77,16.709 22.646,16.709 22.836,16.899 22.836,17.44 22.626,17.65 22.626,17.689 22.436,17.88 v1(22.431,17.88)
NetR33_2: R33.2 U5.9 | length 1.6
  TOP w0.15: R33.2@13.104,14.731 13.104,14.992 13.348,15.235 U5.9@14.39,15.235
NetR34_1: R34.1 SJ2.2 | length 1.9
  TOP w0.127: v1(39.072,16.39) 39.125,16.442 39.202,16.442 39.4,16.64 R34.1@39.4,16.856
  BOTTOM w0.127: v1(39.072,16.39) 39.072,15.966 39.269,15.769 SJ2.2@39.783,15.769
NetR36_1: R36.1 U1.L1 U7.1 | length 8.4
  TOP w0.127: R36.1@21.964,6.006 21.964,6.22 22.135,6.39 22.443,6.39 v1(22.48,6.354) ; v1@22.48,6.374 22.501,6.354 23.045,6.354 23.132,6.267 U7.1@23.132,6.171 ; v1(27.253,6.593) 27.253,6.667 27.119,6.801 27.119,7.35 27.391,7.622 27.391,7.658 27.502,7.77 U1.L1@27.502,7.83
  L3_SIG w0.127: v1(22.48,6.354) 22.496,6.338 22.934,6.338 23.477,5.796 24.612,5.796 24.66,5.747 26.403,5.747 27.249,6.593 v1(27.253,6.593)
NetR37_2: R37.2 U1.K1 U7.3 | length 5.8
  TOP w0.127: U7.3@24.432,6.171 24.432,5.807 24.559,5.68 25.394,5.68 25.989,6.276 25.989,6.664 25.908,6.746 25.908,7.54 26.083,7.715 R37.2@26.269,7.715 26.269,8.107 26.792,8.63 U1.K1@27.502,8.63
NetR38_2: R38.2 U1.B6 | length 7.3
  TOP w0.127: U1.B6@31.502,15.03 31.928,15.455 31.928,15.913 v2(31.913,15.928) v2(31.913,15.928) ; R38.2@36.829,16.856 36.836,16.848 36.836,16.465 v2(36.844,16.458)
  L2_GND w0.127: v2(31.913,15.928) 34.001,15.928 34.092,16.02 34.174,16.02 34.849,16.695 35.634,16.695 35.916,16.977 36.663,16.977 36.844,16.796 v2(36.844,16.458)
NetR39_1: R39.1 U6.1 | length 1
  TOP w0.15: U6.1@10.997,15.625 10.997,14.943 11.143,14.797 11.155,14.797 11.235,14.718 R39.1@11.235,14.706
NetR42_1: R42.1 U3.4 | length 1.9
  TOP w0.127: R42.1@20.565,6.006 20.645,6.087 20.779,6.087 21.077,6.385 21.077,7.618 U3.4@21.089,7.63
